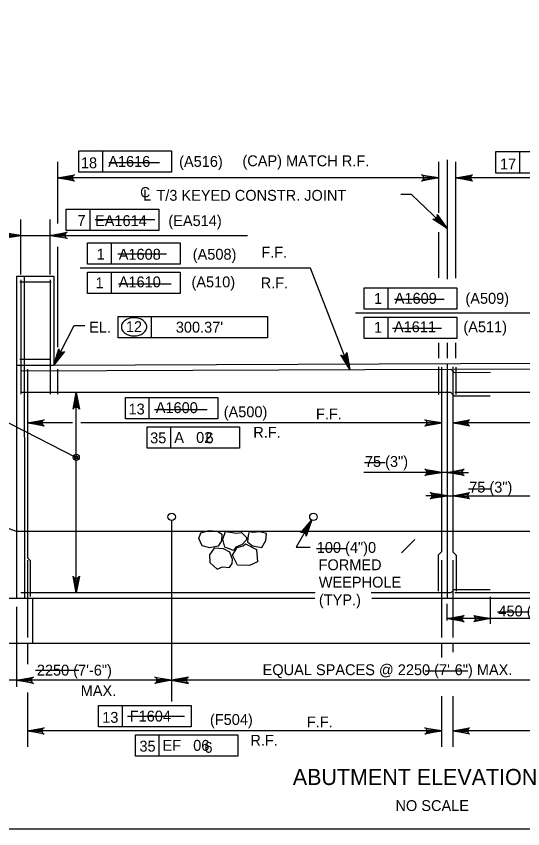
# Model space of a CAD drawing. Extents: x 179 to 454, y -271 to 54.
# Drawn here: x 252.85 to 258.44, y -43.25 to -34.28 of the extents above; entities that cross this region are included whole.
import ezdxf

# ---------------------------------------------------------------- set-up
doc = ezdxf.new("R2010")
doc.units = 0
for name, color, linetype in [('Level 1', 7, 'Continuous'), ('Level 10', 7, 'Continuous'), ('Level 3', 7, 'Continuous'), ('Level 4', 7, 'Continuous'), ('Level 41', 7, 'Continuous'), ('Level 5', 7, 'Continuous')]:
    doc.layers.add(name, color=color, linetype=linetype)

# ---------------------------------------------------------------- blocks, each defined once
blk = doc.blocks.new('ROCK')
at = {"layer": 'Level 4'}
for points in [[(1.578, 0.725), (1.471, 0.551), (1.586, 0.338), (1.78, 0.206), (2.086, 0.269), (2.323, 0.452), (2.328, 0.749), (2.171, 0.911), (1.856, 0.872)], [(0.734, -0.018), (0.934, -0.106), (1.192, -0.099), (1.321, -0.177), (1.562, 0.063), (1.519, 0.367), (1.313, 0.589), (0.948, 0.369), (0.769, 0.319), (0.674, 0.055)], [(0.498, 0.24), (0.588, 0.107), (0.715, -0.096), (0.595, -0.305), (0.299, -0.506), (0.067, -0.329), (-0.063, -0.098), (0.135, 0.068), (0.386, 0.147)], [(1.488, -0.478), (1.468, -0.178), (1.636, 0.025), (1.939, 0.193), (2.2, 0.032), (2.312, -0.229), (2.154, -0.57), (1.947, -0.574), (1.718, -0.703), (1.56, -0.603)], [(0.806, -0.129), (0.519, -0.492), (0.672, -0.928), (0.991, -0.931), (1.399, -0.738), (1.422, -0.324), (1.149, -0.136), (0.916, -0.16)]]:
    blk.add_lwpolyline(points, close=True, dxfattribs=at)

msp = doc.modelspace()

# ---------------------------------------------------------------- linework, layer by layer
at = {"layer": 'Level 1'}
msp.add_lwpolyline([(245.497, -43.25), (276.997, -43.25), (276.997, -22.75), (245.497, -22.75)], close=True, dxfattribs=at)
at = {"layer": 'Level 10'}
for p, q in [((257.6044, -35.8643), (257.6044, -37.1826)), ((252.8528, -37.1499), (252.8528, -40.708)), ((252.8528, -37.1499), (253.2627, -37.1499)), ((252.9372, -37.1499), (252.9385, -40.708)), ((253.2627, -37.1499), (253.2639, -38.1317)), ((257.6044, -37.8444), (257.6044, -37.8444)), ((257.6044, -37.8843), (257.6044, -38.0541)), ((253.2639, -38.1317), (261.9457, -38.0948)), ((257.6044, -38.1163), (257.6044, -38.1164)), ((257.6044, -38.1193), (257.6044, -40.708)), ((252.8574, -38.1334), (253.2639, -38.1317)), ((252.8528, -39.9698), (249.8606, -38.8379)), ((253.6367, -39.9698), (252.8574, -39.9698)), ((262.0111, -39.9698), (253.6367, -39.9698)), ((256.145, -40.708), (249.6966, -40.708)), ((253.0282, -40.708), (253.0282, -41.2001)), ((259.0207, -40.708), (256.7722, -40.708)), ((249.6966, -41.2001), (264.9454, -41.2001))]:
    msp.add_line(p, q, dxfattribs=at)
at = {"layer": 'Level 3'}
for p, q in [((253.5401, -35.7651), (254.5616, -35.7651)), ((253.5401, -36.0012), (253.5401, -35.7651)), ((253.8037, -36.0012), (253.8037, -35.7651)), ((254.5616, -35.7651), (254.5616, -36.0012)), ((258.1427, -35.774), (259.1642, -35.774)), ((258.1427, -36.0102), (258.1427, -35.774)), ((258.4064, -36.0102), (258.4064, -35.774)), ((253.305, -35.8865), (253.305, -36.5688)), ((257.5082, -35.8865), (257.5082, -36.4495)), ((257.699, -37.1713), (257.699, -35.8865)), ((254.5616, -36.0012), (253.5401, -36.0012)), ((259.1642, -36.0102), (258.1427, -36.0102)), ((257.5082, -36.0642), (253.305, -36.0642)), ((261.8995, -36.0642), (257.699, -36.0642)), ((257.2099, -36.2462), (257.0918, -36.2462)), ((257.6044, -36.6217), (257.2099, -36.2462)), ((253.3992, -36.4099), (254.4207, -36.4099)), ((253.3992, -36.6461), (253.3992, -36.4099)), ((253.6629, -36.6461), (253.6629, -36.4099)), ((254.4207, -36.4099), (254.4207, -36.6461)), ((252.8972, -37.1294), (252.8984, -36.5225)), ((253.2216, -37.1294), (253.2228, -36.5225)), ((254.4207, -36.6461), (253.3992, -36.6461)), ((257.5082, -36.6622), (257.5082, -37.1663)), ((252.8981, -36.6997), (252.6623, -36.6997)), ((252.8984, -36.6997), (253.2228, -36.6997)), ((253.2225, -36.6997), (255.4021, -36.6997)), ((253.341, -36.6997), (253.4591, -36.6997)), ((253.305, -36.8242), (253.305, -37.9339)), ((253.6341, -36.7812), (254.6556, -36.7812)), ((253.6341, -37.0174), (253.6341, -36.7812)), ((253.8978, -37.0174), (253.8978, -36.7812)), ((254.6556, -36.7812), (254.6556, -37.0174)), ((254.6556, -37.0174), (253.6341, -37.0174)), ((256.0962, -37.0611), (253.5537, -37.0611)), ((253.6341, -37.1044), (254.6556, -37.1044)), ((253.6341, -37.3407), (253.6341, -37.1044)), ((253.8978, -37.3407), (253.8978, -37.1044)), ((254.6556, -37.1044), (254.6556, -37.3407)), ((256.5302, -38.1793), (256.0962, -37.0611)), ((256.6895, -37.2768), (257.7111, -37.2768)), ((256.6895, -37.5131), (256.6895, -37.2768)), ((256.9532, -37.5131), (256.9532, -37.2768)), ((257.7111, -37.2768), (257.7111, -37.5131)), ((254.6556, -37.3407), (253.6341, -37.3407)), ((259.2046, -37.5568), (256.5932, -37.5568)), ((257.7111, -37.5131), (256.6895, -37.5131)), ((253.9737, -37.5942), (254.3407, -37.5942)), ((253.9737, -37.8304), (253.9737, -37.5942)), ((254.3407, -37.8304), (254.3407, -37.5942)), ((254.3407, -37.5942), (255.6222, -37.5942)), ((255.6222, -37.5942), (255.6222, -37.8304)), ((256.6895, -37.8362), (256.6895, -37.6001)), ((256.6895, -37.6001), (257.7111, -37.6001)), ((256.9532, -37.8362), (256.9532, -37.6001)), ((257.7111, -37.6001), (257.7111, -37.8362)), ((253.2639, -38.1317), (253.4864, -37.6949)), ((253.4864, -37.6949), (253.6045, -37.6949)), ((255.6222, -37.8304), (253.9737, -37.8304)), ((257.7111, -37.8362), (256.6895, -37.8362)), ((257.5082, -37.8843), (257.5082, -38.0541)), ((257.699, -38.0541), (257.699, -37.8843)), ((253.5103, -40.6465), (253.5103, -38.4319)), ((254.0525, -38.4892), (255.074, -38.4892)), ((254.0525, -38.7255), (254.0525, -38.4892)), ((254.3162, -38.7255), (254.3162, -38.4892)), ((255.074, -38.4892), (255.074, -38.7255)), ((257.5429, -38.6463), (257.5429, -38.7713)), ((252.6122, -38.6908), (253.5104, -39.15)), ((255.074, -38.7255), (254.0525, -38.7255)), ((253.47, -38.7692), (252.9709, -38.7692)), ((257.5429, -38.7692), (253.562, -38.7692)), ((254.2921, -39.0487), (254.2921, -38.8125)), ((254.2921, -38.8125), (255.3136, -38.8125)), ((254.5557, -39.0487), (254.5557, -38.8125)), ((255.3136, -38.8125), (255.3136, -39.0487)), ((261.6557, -38.7692), (257.6659, -38.7692)), ((255.3136, -39.0487), (254.2921, -39.0487)), ((257.3067, -39.3155), (256.6862, -39.3155)), ((257.5429, -39.3155), (257.3067, -39.3155)), ((257.6044, -39.3155), (257.5429, -39.3155)), ((257.6044, -39.3155), (257.8407, -39.3155)), ((257.6044, -39.5727), (257.3682, -39.5727)), ((257.6044, -39.5727), (257.6659, -39.5727)), ((257.6659, -39.5727), (257.9022, -39.5727)), ((257.9022, -39.5727), (258.6038, -39.5727)), ((256.1119, -39.8406), (255.9377, -40.1401)), ((257.0996, -40.2054), (257.2471, -40.0579)), ((255.9377, -40.1401), (256.0927, -40.1401)), ((258.0809, -40.9868), (258.0809, -40.6903)), ((252.8529, -40.7983), (252.8529, -41.684)), ((257.6044, -40.9524), (257.6044, -40.7665)), ((259.4417, -40.9298), (257.6044, -40.9298)), ((252.9709, -41.2001), (252.9709, -41.431)), ((257.5429, -41.2001), (257.5429, -41.3607)), ((257.6659, -41.2001), (257.6659, -41.3021)), ((262.1498, -41.6097), (250.9023, -41.6097)), ((252.9709, -41.7472), (252.9709, -42.3463)), ((257.5429, -41.7855), (257.5429, -42.3463)), ((257.6659, -41.7855), (257.6659, -42.3463)), ((253.7569, -41.8892), (254.7784, -41.8892)), ((253.7569, -42.1254), (253.7569, -41.8892)), ((254.0206, -42.1254), (254.0206, -41.8892)), ((254.7784, -41.8892), (254.7784, -42.1254)), ((254.7784, -42.1254), (253.7569, -42.1254)), ((257.5429, -42.1691), (252.9708, -42.1691)), ((254.1629, -42.4486), (254.1629, -42.2124)), ((254.1629, -42.2124), (255.2952, -42.2124)), ((254.4266, -42.4486), (254.4266, -42.2124)), ((255.2952, -42.2124), (255.2952, -42.4486)), ((262.0361, -42.1691), (257.6659, -42.1691)), ((255.2952, -42.4486), (254.1629, -42.4486))]:
    msp.add_line(p, q, dxfattribs=at)
for points in [[(253.305, -36.0642), (253.4914, -36.0292), (253.4771, -36.0392), (253.4697, -36.0517), (253.4675, -36.0642), (253.4697, -36.0767), (253.4771, -36.0892), (253.4914, -36.0991), (253.305, -36.0642), (253.4771, -36.0892), (253.4697, -36.0767), (253.305, -36.0642), (253.4675, -36.0642), (253.4697, -36.0517), (253.305, -36.0642), (253.4771, -36.0392)], [(257.5082, -36.0642), (257.3218, -36.0991), (257.3361, -36.0892), (257.3435, -36.0767), (257.3457, -36.0642), (257.3435, -36.0517), (257.3361, -36.0392), (257.3218, -36.0292), (257.5082, -36.0642), (257.3361, -36.0392), (257.3435, -36.0517), (257.5082, -36.0642), (257.3457, -36.0642), (257.3435, -36.0767), (257.5082, -36.0642), (257.3361, -36.0892)], [(257.699, -36.0642), (257.8854, -36.0292), (257.8711, -36.0392), (257.8637, -36.0517), (257.8615, -36.0642), (257.8637, -36.0767), (257.8711, -36.0892), (257.8854, -36.0991), (257.699, -36.0642), (257.8711, -36.0892), (257.8637, -36.0767), (257.699, -36.0642), (257.8615, -36.0642), (257.8637, -36.0517), (257.699, -36.0642), (257.8711, -36.0392)], [(257.6044, -36.6217), (257.4453, -36.5185), (257.4626, -36.5212), (257.4765, -36.5172), (257.4867, -36.5097), (257.4937, -36.4991), (257.497, -36.4849), (257.4935, -36.4678), (257.6044, -36.6217), (257.497, -36.4849), (257.4937, -36.4991), (257.6044, -36.6217), (257.4867, -36.5097), (257.4765, -36.5172), (257.6044, -36.6217), (257.4626, -36.5212)], [(252.8981, -36.6997), (252.7117, -36.7346), (252.726, -36.7247), (252.7334, -36.7122), (252.7356, -36.6997), (252.7334, -36.6872), (252.726, -36.6747), (252.7117, -36.6647), (252.8981, -36.6997), (252.726, -36.6747), (252.7334, -36.6872), (252.8981, -36.6997), (252.7356, -36.6997), (252.7334, -36.7122), (252.8981, -36.6997), (252.726, -36.7247)], [(253.2225, -36.6997), (253.4089, -36.6647), (253.3946, -36.6747), (253.3872, -36.6872), (253.385, -36.6997), (253.3872, -36.7122), (253.3946, -36.7247), (253.4089, -36.7346), (253.2225, -36.6997), (253.3946, -36.7247), (253.3872, -36.7122), (253.2225, -36.6997), (253.385, -36.6997), (253.3872, -36.6872), (253.2225, -36.6997), (253.3946, -36.6747)], [(253.2639, -38.1317), (253.3174, -37.9498), (253.3197, -37.9671), (253.3275, -37.9793), (253.3377, -37.9869), (253.3498, -37.9907), (253.3642, -37.9898), (253.3797, -37.9815), (253.2639, -38.1317), (253.3642, -37.9898), (253.3498, -37.9907), (253.2639, -38.1317), (253.3377, -37.9869), (253.3275, -37.9793), (253.2639, -38.1317), (253.3197, -37.9671)], [(256.5302, -38.1793), (256.4302, -38.0182), (256.4447, -38.028), (256.459, -38.0303), (256.4714, -38.0278), (256.4823, -38.0213), (256.4913, -38.0099), (256.4953, -37.9929), (256.5302, -38.1793), (256.4913, -38.0099), (256.4823, -38.0213), (256.5302, -38.1793), (256.4714, -38.0278), (256.459, -38.0303), (256.5302, -38.1793), (256.4447, -38.028)], [(253.5103, -38.4319), (253.5452, -38.6183), (253.5353, -38.604), (253.5228, -38.5966), (253.5103, -38.5944), (253.4978, -38.5966), (253.4853, -38.604), (253.4754, -38.6183), (253.5103, -38.4319), (253.4853, -38.604), (253.4978, -38.5966), (253.5103, -38.4319), (253.5103, -38.5944), (253.5228, -38.5966), (253.5103, -38.4319), (253.5353, -38.604)], [(252.9708, -38.7692), (253.1573, -38.7342), (253.1429, -38.7442), (253.1355, -38.7567), (253.1333, -38.7692), (253.1355, -38.7817), (253.1429, -38.7942), (253.1573, -38.8041), (252.9708, -38.7692), (253.1429, -38.7942), (253.1355, -38.7817), (252.9708, -38.7692), (253.1333, -38.7692), (253.1355, -38.7567), (252.9708, -38.7692), (253.1429, -38.7442)], [(257.5429, -38.7692), (257.3565, -38.8041), (257.3708, -38.7942), (257.3782, -38.7817), (257.3804, -38.7692), (257.3782, -38.7567), (257.3708, -38.7442), (257.3565, -38.7342), (257.5429, -38.7692), (257.3708, -38.7442), (257.3782, -38.7567), (257.5429, -38.7692), (257.3804, -38.7692), (257.3782, -38.7817), (257.5429, -38.7692), (257.3708, -38.7942)], [(257.6659, -38.7692), (257.8523, -38.7342), (257.838, -38.7442), (257.8306, -38.7567), (257.8284, -38.7692), (257.8306, -38.7817), (257.838, -38.7942), (257.8523, -38.8041), (257.6659, -38.7692), (257.838, -38.7942), (257.8306, -38.7817), (257.6659, -38.7692), (257.8284, -38.7692), (257.8306, -38.7567), (257.6659, -38.7692), (257.838, -38.7442)], [(257.5429, -39.3155), (257.3565, -39.3504), (257.3708, -39.3405), (257.3782, -39.328), (257.3804, -39.3155), (257.3782, -39.303), (257.3708, -39.2905), (257.3565, -39.2806), (257.5429, -39.3155), (257.3708, -39.2905), (257.3782, -39.303), (257.5429, -39.3155), (257.3804, -39.3155), (257.3782, -39.328), (257.5429, -39.3155), (257.3708, -39.3405)], [(257.6044, -39.3155), (257.7908, -39.2806), (257.7765, -39.2905), (257.7691, -39.303), (257.7669, -39.3155), (257.7691, -39.328), (257.7765, -39.3405), (257.7908, -39.3505), (257.6044, -39.3155), (257.7765, -39.3405), (257.7691, -39.328), (257.6044, -39.3155), (257.7669, -39.3155), (257.7691, -39.303), (257.6044, -39.3155), (257.7765, -39.2905)], [(257.6044, -39.5727), (257.418, -39.6076), (257.4323, -39.5977), (257.4398, -39.5852), (257.4419, -39.5727), (257.4398, -39.5602), (257.4323, -39.5477), (257.418, -39.5377), (257.6044, -39.5727), (257.4323, -39.5477), (257.4398, -39.5602), (257.6044, -39.5727), (257.4419, -39.5727), (257.4398, -39.5852), (257.6044, -39.5727), (257.4323, -39.5977)], [(257.6659, -39.5727), (257.8523, -39.5377), (257.838, -39.5477), (257.8306, -39.5602), (257.8284, -39.5727), (257.8306, -39.5852), (257.838, -39.5977), (257.8523, -39.6076), (257.6659, -39.5727), (257.838, -39.5977), (257.8306, -39.5852), (257.6659, -39.5727), (257.8284, -39.5727), (257.8306, -39.5602), (257.6659, -39.5727), (257.838, -39.5477)], [(256.1119, -39.8406), (256.0484, -40.0192), (256.047, -40.0018), (256.0399, -39.9892), (256.0302, -39.981), (256.0183, -39.9766), (256.0037, -39.9767), (255.988, -39.9842), (256.1119, -39.8406), (256.0037, -39.9767), (256.0183, -39.9766), (256.1119, -39.8406), (256.0302, -39.981), (256.0399, -39.9892), (256.1119, -39.8406), (256.047, -40.0018)], [(253.5103, -40.6465), (253.4754, -40.4601), (253.4853, -40.4744), (253.4978, -40.4818), (253.5103, -40.484), (253.5228, -40.4818), (253.5353, -40.4744), (253.5452, -40.4601), (253.5103, -40.6465), (253.5353, -40.4744), (253.5228, -40.4818), (253.5103, -40.6465), (253.5103, -40.484), (253.4978, -40.4818), (253.5103, -40.6465), (253.4853, -40.4744)], [(257.6044, -40.9298), (257.7908, -40.8948), (257.7765, -40.9048), (257.7691, -40.9173), (257.7669, -40.9298), (257.7691, -40.9423), (257.7765, -40.9548), (257.7908, -40.9647), (257.6044, -40.9298), (257.7765, -40.9548), (257.7691, -40.9423), (257.6044, -40.9298), (257.7669, -40.9298), (257.7691, -40.9173), (257.6044, -40.9298), (257.7765, -40.9048)], [(258.0834, -40.9298), (257.897, -40.9647), (257.9114, -40.9548), (257.9188, -40.9423), (257.9209, -40.9298), (257.9188, -40.9173), (257.9114, -40.9048), (257.897, -40.8949), (258.0834, -40.9298), (257.9114, -40.9048), (257.9188, -40.9173), (258.0834, -40.9298), (257.9209, -40.9298), (257.9188, -40.9423), (258.0834, -40.9298), (257.9114, -40.9548)], [(252.9708, -42.1691), (253.1573, -42.1342), (253.1429, -42.1441), (253.1355, -42.1566), (253.1333, -42.1691), (253.1355, -42.1816), (253.1429, -42.1941), (253.1573, -42.204), (252.9708, -42.1691), (253.1429, -42.1941), (253.1355, -42.1816), (252.9708, -42.1691), (253.1333, -42.1691), (253.1355, -42.1566), (252.9708, -42.1691), (253.1429, -42.1441)], [(257.5429, -42.1691), (257.3565, -42.204), (257.3708, -42.1941), (257.3782, -42.1816), (257.3804, -42.1691), (257.3782, -42.1566), (257.3708, -42.1441), (257.3565, -42.1342), (257.5429, -42.1691), (257.3708, -42.1441), (257.3782, -42.1566), (257.5429, -42.1691), (257.3804, -42.1691), (257.3782, -42.1816), (257.5429, -42.1691), (257.3708, -42.1941)], [(257.6659, -42.1691), (257.8523, -42.1342), (257.838, -42.1441), (257.8306, -42.1566), (257.8284, -42.1691), (257.8306, -42.1816), (257.838, -42.1941), (257.8523, -42.204), (257.6659, -42.1691), (257.838, -42.1941), (257.8306, -42.1816), (257.6659, -42.1691), (257.8284, -42.1691), (257.8306, -42.1566), (257.6659, -42.1691), (257.838, -42.1441)]]:
    msp.add_lwpolyline(points, dxfattribs=at)
for points in [[(252.7803, -36.68), (252.7803, -36.7193), (252.8984, -36.6997)], [(253.341, -36.68), (253.341, -36.7193), (253.2228, -36.6997)], [(253.3, -38.0176), (253.3351, -38.0354), (253.2639, -38.1317)], [(256.469, -38.0759), (256.5058, -38.0619), (256.5292, -38.1793)], [(253.53, -38.55), (253.4907, -38.55), (253.5103, -38.4319)], [(257.4248, -38.7494), (257.4248, -38.7888), (257.5429, -38.7692)], [(257.7841, -38.7494), (257.7841, -38.7888), (257.6659, -38.7692)], [(257.4248, -39.2958), (257.4248, -39.3352), (257.5429, -39.3155)], [(257.7225, -39.2958), (257.7225, -39.3352), (257.6044, -39.3155)], [(257.4863, -39.553), (257.4863, -39.5924), (257.6044, -39.5727)], [(257.7841, -39.553), (257.7841, -39.5924), (257.6659, -39.5727)], [(256.0698, -39.952), (256.0358, -39.9322), (256.1122, -39.84)], [(253.53, -40.5283), (253.4907, -40.5283), (253.5103, -40.6465)], [(257.4248, -42.1494), (257.4248, -42.1887), (257.5429, -42.1691)], [(257.7841, -42.1494), (257.7841, -42.1887), (257.6659, -42.1691)]]:
    msp.add_lwpolyline(points, close=True, dxfattribs=at)
for centre, radius in [((253.5104, -39.15), 0.0333), ((253.5104, -39.15), 0.0167), ((254.5633, -39.8058), 0.041), ((256.1281, -39.8058), 0.041)]:
    msp.add_circle(centre, radius, dxfattribs=at)
for centre, radius, start, end in [((254.0818, -37.7081), 0.0731, 149.97668, 180), ((254.1141, -37.7267), 0.1103, 125.63164, 149.97668), ((254.1351, -37.7561), 0.1465, 106.53583, 125.63164), ((254.1489, -37.8025), 0.1949, 90, 106.53583), ((254.1489, -37.8025), 0.1949, 73.46417, 90), ((254.1627, -37.7561), 0.1465, 54.36836, 73.46417), ((254.1837, -37.7267), 0.1103, 30.02332, 54.36836), ((254.216, -37.7081), 0.0731, 0, 30.02332), ((254.0818, -37.7081), 0.0731, 180, 210.02332), ((254.1141, -37.6894), 0.1103, 210.02332, 234.36836), ((254.1837, -37.6894), 0.1103, 305.63164, 329.97668), ((254.216, -37.7081), 0.0731, 329.97668, 0), ((254.1351, -37.6601), 0.1465, 234.36836, 253.46417), ((254.1489, -37.6137), 0.1949, 253.46417, 270), ((254.1489, -37.6137), 0.1949, 270, 286.53583), ((254.1627, -37.6601), 0.1465, 286.53583, 305.63164)]:
    msp.add_arc(centre, radius, start, end, dxfattribs=at)
at = {"layer": 'Level 4'}
for points in [[(252.8528, -41.6097), (253.0392, -41.5748), (253.0249, -41.5847), (253.0175, -41.5972), (253.0153, -41.6097), (253.0175, -41.6222), (253.0249, -41.6347), (253.0392, -41.6446), (252.8528, -41.6097), (253.0249, -41.6347), (253.0175, -41.6222), (252.8528, -41.6097), (253.0153, -41.6097), (253.0175, -41.5972), (252.8528, -41.6097), (253.0249, -41.5847)], [(254.5632, -41.6097), (254.3768, -41.6446), (254.3912, -41.6347), (254.3986, -41.6222), (254.4007, -41.6097), (254.3986, -41.5972), (254.3912, -41.5847), (254.3768, -41.5748), (254.5632, -41.6097), (254.3912, -41.5847), (254.3986, -41.5972), (254.5632, -41.6097), (254.4007, -41.6097), (254.3986, -41.6222), (254.5632, -41.6097), (254.3912, -41.6347)], [(254.5632, -41.6097), (254.7497, -41.6446), (254.7353, -41.6347), (254.7279, -41.6222), (254.7258, -41.6097), (254.7279, -41.5972), (254.7353, -41.5847), (254.7497, -41.5748), (254.5632, -41.6097), (254.7353, -41.5847), (254.7279, -41.5972), (254.5632, -41.6097), (254.7258, -41.6097), (254.7279, -41.6222), (254.5632, -41.6097), (254.7353, -41.6347)]]:
    msp.add_lwpolyline(points, dxfattribs=at)
at = {"layer": 'Level 41'}
for p, q in [((253.8685, -35.8936), (254.4279, -35.8936)), ((253.7186, -36.5234), (254.3779, -36.5234)), ((253.9684, -36.9033), (254.5078, -36.9033)), ((253.9784, -37.2332), (254.5578, -37.2332)), ((257.022, -37.4033), (257.5714, -37.4033)), ((257.002, -37.7232), (257.5415, -37.7232)), ((254.3758, -38.6203), (254.9552, -38.6203)), ((256.6913, -39.2074), (256.921, -39.2074)), ((257.8401, -39.4973), (258.0798, -39.4973)), ((256.1618, -40.1571), (256.5015, -40.1571)), ((258.1597, -40.8568), (258.5094, -40.8568)), ((253.0596, -41.4988), (253.5391, -41.4988)), ((257.3623, -41.5065), (257.8318, -41.5065)), ((254.0757, -42.0064), (254.705, -42.0064))]:
    msp.add_line(p, q, dxfattribs=at)
at = {"layer": 'Level 5'}
for p, q in [((252.8869, -37.2114), (253.2319, -37.2114)), ((252.8972, -37.1909), (252.8984, -38.4524)), ((253.2216, -37.1909), (253.2228, -38.4524)), ((253.2305, -38.0704), (252.8882, -38.0704)), ((252.8984, -38.1948), (257.6459, -38.1746)), ((252.9708, -38.1742), (252.9708, -40.2583)), ((253.3053, -38.1745), (253.305, -38.4524)), ((257.5083, -38.1517), (257.508, -38.4566)), ((257.5429, -38.1527), (257.5429, -40.1932)), ((257.6459, -38.1746), (257.6833, -38.2119)), ((257.6659, -38.1518), (257.6659, -40.1932)), ((257.6832, -38.1744), (262.1133, -38.1556)), ((257.6833, -38.2119), (258.0809, -38.2102)), ((257.6991, -38.1519), (257.6988, -38.4568)), ((257.6454, -38.4319), (252.8984, -38.4319)), ((257.6454, -38.4319), (257.6827, -38.4693)), ((257.6827, -38.4693), (258.0803, -38.4693)), ((262.1133, -38.4319), (257.6875, -38.4319)), ((254.5632, -39.8468), (254.5632, -41.8441)), ((252.9708, -40.2583), (253.0002, -40.2875)), ((257.5429, -40.1932), (257.5055, -40.2304)), ((257.5055, -40.2304), (257.5055, -40.6281)), ((257.6659, -40.1932), (257.7034, -40.2304)), ((257.7034, -40.2304), (257.7034, -40.6281)), ((252.9708, -40.2861), (252.9708, -41.1386)), ((253.0002, -40.2875), (253.0002, -40.6852)), ((257.5429, -40.2861), (257.5429, -41.1386)), ((257.6659, -40.2861), (257.6659, -41.1386)), ((257.6454, -40.6465), (257.6827, -40.6091)), ((257.6827, -40.6091), (258.0803, -40.6091)), ((256.148, -40.6465), (252.8984, -40.6465)), ((257.6454, -40.6465), (256.7647, -40.6465)), ((258.6443, -40.6465), (257.6875, -40.6465))]:
    msp.add_line(p, q, dxfattribs=at)

# ---------------------------------------------------------------- block references
at = {"layer": 'Level 3', "xscale": 0.2952750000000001, "yscale": -0.29527500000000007, "rotation": -156.2166383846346}
msp.add_blockref('ROCK', (255.5811, -39.9722), dxfattribs=at)

# ---------------------------------------------------------------- texts
at = {"layer": 'Level 3'}
for s, height, p in [('A1616', 0.12, (253.8637, -35.942)), ('(A516)', 0.12, (254.6459, -35.942)), ('(CAP) MATCH R.F.', 0.12, (255.3446, -35.9353)), ('C', 0.1137, (254.2154, -36.2792)), ('L', 0.12, (254.2474, -36.3148)), ('T/3 KEYED CONSTR. JOINT', 0.12, (254.3953, -36.3166)), ('EA1614', 0.12, (253.7175, -36.5959)), ('(EA514)', 0.12, (254.5274, -36.5959)), ('A1608', 0.12, (253.9795, -36.9672)), ('(A508)', 0.12, (254.7963, -36.9672)), ('F.F.', 0.12, (255.553, -36.9449)), ('A1610', 0.12, (253.9795, -37.2724)), ('(A510)', 0.12, (254.7825, -37.2724)), ('R.F.', 0.12, (255.546, -37.2821)), ('A1609', 0.12, (257.0259, -37.4537)), ('(A509)', 0.12, (257.8056, -37.4537)), ('EL.', 0.12, (253.653, -37.7712)), ('12', 0.12, (254.0582, -37.7666)), ('A1611', 0.12, (257.0168, -37.768)), ('(A511)', 0.12, (257.7832, -37.768)), ('A1600', 0.12, (254.3881, -38.6607)), ('(A500)', 0.12, (255.1381, -38.7066)), ('F.F.', 0.12, (256.1562, -38.7308)), ('R.F.', 0.12, (255.4646, -38.9333)), ('A   02', 0.12, (254.5925, -38.9894)), ('75 (3")', 0.12, (256.6966, -39.255)), ('75 (3")', 0.12, (257.8474, -39.5379)), ('100 (4")0', 0.12, (256.1652, -40.2044)), ('FORMED', 0.12, (256.1851, -40.3957)), ('WEEPHOLE', 0.12, (256.1871, -40.5869)), ('(TYP.)', 0.12, (256.1888, -40.7819)), ('450 (1\'-6")', 0.12, (258.1701, -40.9053)), ('2250 (7\'-6")', 0.12, (253.0757, -41.5585)), ('EQUAL SPACES @ 2250 (7\'-6") MAX.', 0.12, (255.5675, -41.5542)), ('MAX.', 0.12, (253.5597, -41.7847)), ('F1604', 0.12, (254.1008, -42.0661)), ('(F504)', 0.12, (254.9862, -42.104)), ('F.F.', 0.12, (256.056, -42.1307)), ('R.F.', 0.12, (255.432, -42.3332)), ('EF   06', 0.12, (254.4625, -42.3893)), ('ABUTMENT ELEVATION', 0.177167, (255.9003, -42.7668)), ('NO SCALE', 0.12, (257.0337, -43.0543))]:
    msp.add_text(s, height=height, dxfattribs=at).set_placement(p)
at = {"layer": 'Level 41'}
for s, p in [('18', (253.5622, -35.9571)), ('17', (258.1869, -35.9703)), ('7', (253.5244, -36.5936)), ('1', (253.7364, -36.9649)), ('1', (253.7232, -37.2832)), ('1', (256.7975, -37.4555)), ("300.37'", (254.6094, -37.7721)), ('1', (256.7975, -37.7737)), ('13', (254.0876, -38.6758)), ('35', (254.3261, -38.9941)), ('6', (254.9377, -38.9941)), ('13', (253.797, -42.0802)), ('35', (254.2078, -42.3984)), ('6', (254.9253, -42.4117))]:
    msp.add_text(s, height=0.12, dxfattribs=at).set_placement(p)

doc.saveas('drawing.dxf')
